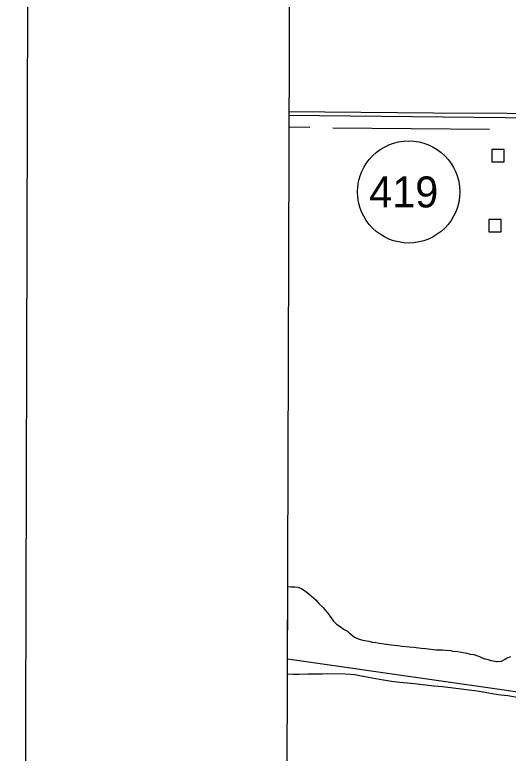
# Model space of a CAD drawing. Extents: x 3161514 to 3199414, y 831166 to 856601.
# Drawn here: x 3164849 to 3166442, y 844788 to 847172 of the extents above; entities that cross this region are included whole.
import ezdxf

# ---------------------------------------------------------------- set-up
doc = ezdxf.new("R2010")
doc.units = 0
for name, color, linetype in [('V-ANNO-SYMB', 7, 'Continuous'), ('V-BLDG-OTLN', 7, 'Continuous'), ('V-GRID-FRAM', 7, 'Continuous'), ('V-ROAD-CNTR', 7, 'Continuous'), ('V-ROAD-IDEN', 7, 'Continuous'), ('V-SITE-VEGE', 7, 'Continuous'), ('V-TOPO-SHOR', 7, 'Continuous')]:
    doc.layers.add(name, color=color, linetype=linetype)

msp = doc.modelspace()

# ---------------------------------------------------------------- linework, layer by layer
at = {"layer": 'V-ANNO-SYMB'}
msp.add_lwpolyline([(3164849.4, 832468.6), (3197932.5, 832377.2), (3197995.8, 855293.6), (3164912.7, 855385), (3164849.4, 832468.6)], dxfattribs=at)
at = {"layer": 'V-BLDG-OTLN'}
for points in [[(3166389, 846697.5), (3166429, 846697.5), (3166429, 846737.5), (3166389, 846737.5)], [(3166379.7, 846471.7), (3166419.7, 846471.7), (3166419.7, 846511.7), (3166379.7, 846511.7)]]:
    msp.add_lwpolyline(points, close=True, dxfattribs=at)
at = {"layer": 'V-GRID-FRAM'}
msp.add_lwpolyline([(3165761, 854820), (3197144.3, 854733.3), (3197102, 836546.1), (3165702.9, 836632.9), (3165761, 854820)], dxfattribs=at)
at = {"layer": 'V-ROAD-CNTR'}
msp.add_lwpolyline([(3170151.9, 847903.9), (3169724.4, 847758.9), (3169462.6, 847671.1), (3168835.2, 847458.3), (3168026.5, 847183), (3167443.5, 846986.7), (3167154.8, 846885.7), (3167072.1, 846866.3), (3167005.7, 846848.1), (3166944.1, 846842.2), (3166869.4, 846839.3), (3166632.7, 846838), (3165733.5, 846846.7)], dxfattribs=at)
at = {"layer": 'V-ROAD-IDEN'}
msp.add_circle((3166121.1, 846600.4), 165, dxfattribs=at)
at = {"layer": 'V-SITE-VEGE'}
for p, q in [((3165729.8, 845043.6), (3165730.7, 845326)), ((3165730.7, 845326), (3165740.9, 845325.1)), ((3165740.9, 845325.1), (3165753.6, 845324.9)), ((3165753.6, 845324.9), (3165763.9, 845323.9)), ((3165763.9, 845323.9), (3165775.7, 845318.7)), ((3165775.7, 845318.7), (3165784.2, 845313.4)), ((3165784.2, 845313.4), (3165793.4, 845307.3)), ((3165793.4, 845307.3), (3165806.1, 845296.1)), ((3165806.1, 845296.1), (3165822.1, 845282.2)), ((3165822.1, 845282.2), (3165831.3, 845271.9)), ((3165831.3, 845271.9), (3165844.8, 845258.9)), ((3165844.8, 845258.9), (3165851.5, 845250.3)), ((3165851.5, 845250.3), (3165859, 845241.7)), ((3165859, 845241.7), (3165865.7, 845233.1)), ((3165865.7, 845233.1), (3165877.4, 845215)), ((3165877.4, 845215), (3165887.5, 845204.6)), ((3165887.5, 845204.6), (3165902.7, 845195)), ((3165902.7, 845195), (3165911.1, 845189)), ((3165911.1, 845189), (3165923.8, 845182)), ((3165923.8, 845182), (3165930.5, 845175.1)), ((3165930.5, 845175.1), (3165939.8, 845168.1)), ((3165939.8, 845168.1), (3165946.5, 845162.9)), ((3165946.5, 845162.9), (3165960.9, 845156.8)), ((3165960.9, 845156.8), (3165972.8, 845153.2)), ((3165972.8, 845153.2), (3165992.4, 845149.5)), ((3165992.4, 845149.5), (3166003.4, 845146.8)), ((3166003.4, 845146.8), (3166015.3, 845145.8)), ((3166015.3, 845145.8), (3166027.2, 845143.1)), ((3166027.2, 845143.1), (3166049.3, 845140.2)), ((3166049.3, 845140.2), (3166064.6, 845138.3)), ((3166064.6, 845138.3), (3166085.9, 845136.3)), ((3166085.9, 845136.3), (3166099.5, 845133.5)), ((3166099.5, 845133.5), (3166122.5, 845131.5)), ((3166122.5, 845131.5), (3166137.8, 845130.5)), ((3166137.8, 845130.5), (3166160.8, 845127.6)), ((3166160.8, 845127.6), (3166175.3, 845126.5)), ((3166175.3, 845126.5), (3166210.1, 845121.8)), ((3166210.1, 845121.8), (3166229.7, 845121.5)), ((3166229.7, 845121.5), (3166239.9, 845120.5)), ((3166239.9, 845120.5), (3166257, 845119.4)), ((3166257, 845119.4), (3166262.9, 845117.7)), ((3166262.9, 845117.7), (3166279.9, 845116.6)), ((3166279.9, 845116.6), (3166291.8, 845114.7)), ((3166291.8, 845114.7), (3166308.8, 845111.1)), ((3166308.8, 845111.1), (3166319.9, 845108.3)), ((3166319.9, 845108.3), (3166331.8, 845106.5)), ((3166331.8, 845106.5), (3166340.3, 845103.8)), ((3166340.3, 845103.8), (3166351.3, 845099.4)), ((3166351.3, 845099.4), (3166358, 845095.9)), ((3166358, 845095.9), (3166367.4, 845092.4)), ((3166367.4, 845092.4), (3166373.3, 845091.4)), ((3166373.3, 845091.4), (3166386, 845087)), ((3166386, 845087), (3166393.7, 845086)), ((3166393.7, 845086), (3166404.7, 845084.2)), ((3166408.2, 845084.1), (3166421, 845085.6)), ((3166421, 845085.6), (3166433, 845091.4)), ((3166433, 845091.4), (3166439, 845096.5)), ((3166439, 845096.5), (3166451, 845100.6)), ((3166404.7, 845084.2), (3166408.2, 845084.1)), ((3165749.7, 845042.1), (3165729.8, 845043.6)), ((3165767.6, 845041.8), (3165749.7, 845042.1)), ((3165795.8, 845043.1), (3165767.6, 845041.8)), ((3165813.7, 845043.7), (3165795.8, 845043.1)), ((3165841.8, 845043.4), (3165813.7, 845043.7)), ((3165860.5, 845044), (3165841.8, 845043.4)), ((3165915.9, 845043.2), (3165860.5, 845044)), ((3165947.4, 845041.1), (3165915.9, 845043.2)), ((3165968.7, 845036.5), (3165947.4, 845041.1)), ((3166003.5, 845030.1), (3165968.7, 845036.5)), ((3166026.5, 845025.5), (3166003.5, 845030.1)), ((3166065.6, 845019.8), (3166026.5, 845025.5)), ((3166092.8, 845016), (3166065.6, 845019.8)), ((3166139.6, 845012), (3166092.8, 845016)), ((3166156.6, 845010), (3166139.6, 845012)), ((3166202.5, 845004.3), (3166156.6, 845010)), ((3166229.8, 845002.2), (3166202.5, 845004.3)), ((3166273.2, 844997.4), (3166229.8, 845002.2)), ((3166342.1, 844987.9), (3166273.2, 844997.4)), ((3166368.4, 844984.1), (3166342.1, 844987.9)), ((3166409.2, 844976.7), (3166368.4, 844984.1)), ((3166440.7, 844972.9), (3166409.2, 844976.7)), ((3166490, 844964.6), (3166440.7, 844972.9))]:
    msp.add_line(p, q, dxfattribs=at)
at = {"layer": 'V-TOPO-SHOR'}
for p, q in [((3165733.2, 846811.1), (3165801.7, 846809.2)), ((3165875.8, 846807.3), (3166381.4, 846803.5))]:
    msp.add_line(p, q, dxfattribs=at)
for points in [[(3166676, 846852.9), (3166200.8, 846854.8), (3165733.2, 846858.6)], [(3165729.3, 845092.5), (3166676.6, 844956.7), (3167273.5, 844877.7), (3167592.4, 844811.4)]]:
    msp.add_lwpolyline(points, dxfattribs=at)

# ---------------------------------------------------------------- texts
at = {"layer": 'V-ROAD-IDEN'}
msp.add_text('419', height=100, dxfattribs=at).set_placement((3165993.5, 846550.4))

doc.saveas('drawing.dxf')
